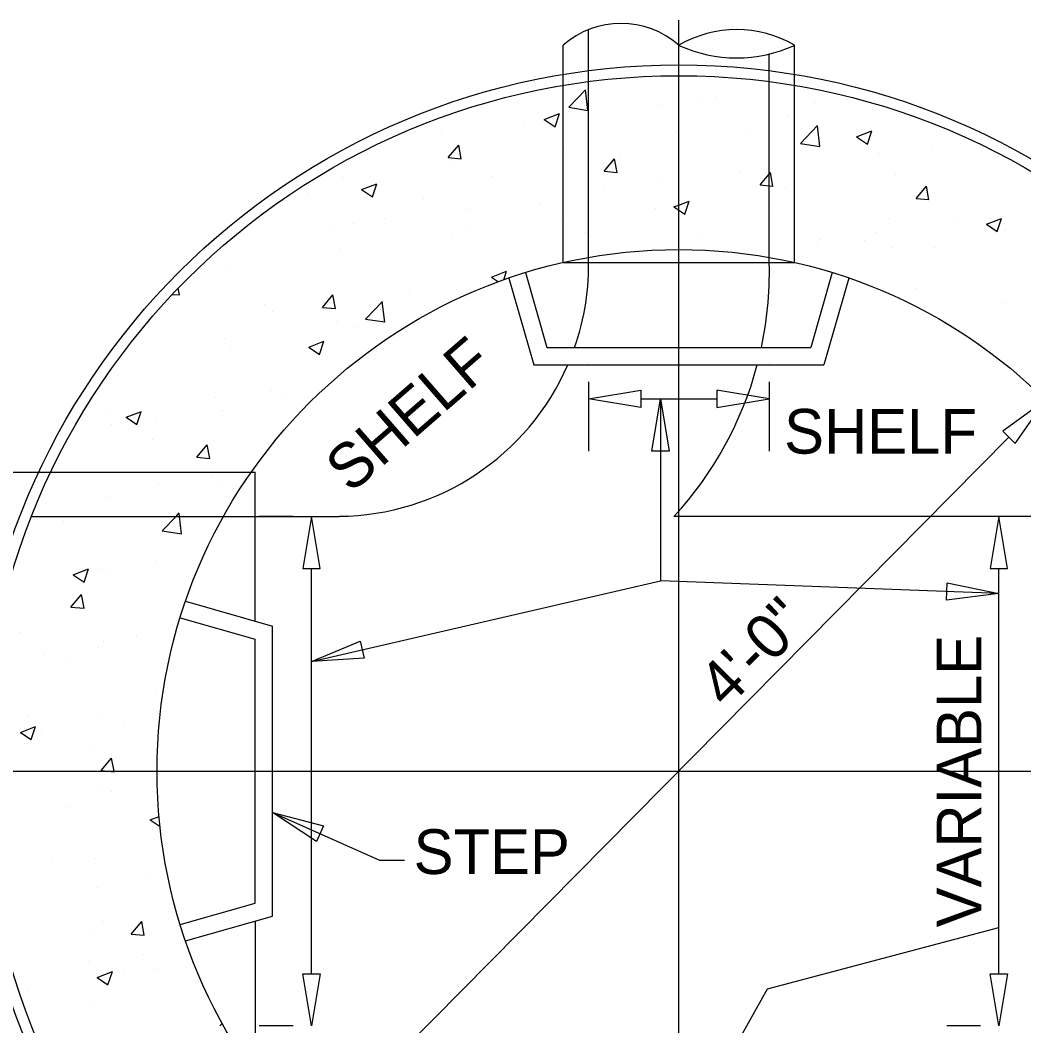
# Model space of a CAD drawing. Extents: x 6712067 to 6713867, y 1867712 to 1869162.
# Drawn here: x 6712906.2 to 6713040.8, y 1867989.4 to 1868124.3 of the extents above; entities that cross this region are included whole.
import ezdxf

# ---------------------------------------------------------------- set-up
doc = ezdxf.new("R2010")
doc.units = 0
for name, color, linetype in [('G-MARK', 7, 'Continuous'), ('G-TEXT', 7, 'Continuous'), ('Misc CnstDet(22)', 7, 'Continuous')]:
    doc.layers.add(name, color=color, linetype=linetype)

msp = doc.modelspace()

# ---------------------------------------------------------------- linework, layer by layer
at = {"layer": 'G-MARK'}
for p, q in [((6712982.44, 1868075.84), (6712982.44, 1868066.53)), ((6712989.44, 1868073.53), (6712999.64, 1868073.53)), ((6712992.07, 1868073.52), (6712992.07, 1868049.11)), ((6713038.81, 1868068.39), (6712950.27, 1867978.84)), ((6712945.28, 1867996.43), (6712945.28, 1868050.79)), ((6712945.28, 1868038.33), (6712992.07, 1868049.11)), ((6713037.47, 1868047.44), (6712992.07, 1868049.11))]:
    msp.add_line(p, q, dxfattribs=at)
msp.add_lwpolyline([(6712940.04, 1868018.07), (6712954.39, 1868011.66), (6712957.74, 1868011.66)], dxfattribs=at)
at = {"layer": 'G-TEXT'}
for points in [[(6712989.44, 1868074.7), (6712989.44, 1868072.36), (6712982.44, 1868073.53)], [(6712999.64, 1868074.7), (6712999.64, 1868072.36), (6713006.64, 1868073.53)], [(6712990.9, 1868066.52), (6712992.07, 1868073.52), (6712993.23, 1868066.52)], [(6713037.97, 1868069.2), (6713039.63, 1868067.56), (6713043.72, 1868073.35)], [(6712944.11, 1868050.79), (6712946.45, 1868050.79), (6712945.28, 1868057.78)], [(6713036.29, 1868050.79), (6713038.62, 1868050.79), (6713037.47, 1868057.78)], [(6713030.51, 1868048.86), (6713037.47, 1868047.44), (6713030.43, 1868046.53)], [(6712952.36, 1868038.76), (6712945.28, 1868038.33), (6712951.83, 1868041.04)], [(6712945.95, 1868014.15), (6712940.04, 1868018.07), (6712946.9, 1868016.28)], [(6712944.11, 1867996.43), (6712946.45, 1867996.43), (6712945.28, 1867989.43)], [(6713036.29, 1867996.43), (6713038.62, 1867996.43), (6713037.47, 1867989.43)]]:
    msp.add_lwpolyline(points, close=True, dxfattribs=at)
at = {"layer": 'Misc CnstDet(22)'}
for p, q in [((6712994.54, 1867921.43), (6712994.54, 1868124.34)), ((6712982.44, 1868092.51), (6712982.44, 1868123.08)), ((6712979.02, 1868091.82), (6712979.02, 1868120.97)), ((6713010.06, 1868091.82), (6713010.06, 1868120.97)), ((6713006.64, 1868092.51), (6713006.64, 1868119.8)), ((6712979.77, 1868112.65), (6712982.04, 1868115.01)), ((6712981.6, 1868114.6), (6712981.6, 1868114.6)), ((6712982.36, 1868112.24), (6712982.04, 1868115.01)), ((6713010.52, 1868115.47), (6713010.52, 1868115.47)), ((6712992.18, 1868113.06), (6712992.18, 1868113.06)), ((6712997.16, 1868113.94), (6712997.16, 1868113.94)), ((6712999.48, 1868114.02), (6712999.48, 1868114.02)), ((6713012.73, 1868113.28), (6713012.73, 1868113.28)), ((6712976.5, 1868111.02), (6712978.54, 1868111.81)), ((6712977.94, 1868110.04), (6712978.54, 1868111.8)), ((6712979.77, 1868112.65), (6712982.36, 1868112.24)), ((6713020.6, 1868112.18), (6713020.6, 1868112.18)), ((6712973.78, 1868110.64), (6712973.78, 1868110.64)), ((6712976.5, 1868111.02), (6712977.94, 1868110.04)), ((6713009.21, 1868111.42), (6713009.21, 1868111.42)), ((6713010.88, 1868107.81), (6713013.14, 1868110.19)), ((6713013.46, 1868107.41), (6713013.14, 1868110.18)), ((6712962.74, 1868109.18), (6712962.74, 1868109.18)), ((6712994.25, 1868109.36), (6712994.25, 1868109.36)), ((6713003.6, 1868109.26), (6713003.6, 1868109.26)), ((6713018.38, 1868108.69), (6713020.43, 1868109.47)), ((6713019.84, 1868107.7), (6713020.43, 1868109.47)), ((6712955.44, 1868108.22), (6712955.44, 1868108.22)), ((6712963.62, 1868105.9), (6712965.02, 1868107.57)), ((6712965.36, 1868105.75), (6712965.02, 1868107.57)), ((6713010.88, 1868107.81), (6713013.46, 1868107.41)), ((6713018.38, 1868108.69), (6713019.84, 1868107.71)), ((6712979.1, 1868107.17), (6712979.1, 1868107.17)), ((6712986.61, 1868106.35), (6712986.61, 1868106.35)), ((6713021.26, 1868106.4), (6713021.26, 1868106.4)), ((6713028.56, 1868107.36), (6713028.56, 1868107.36)), ((6712963.62, 1868105.9), (6712965.36, 1868105.75)), ((6712964.38, 1868105.31), (6712964.38, 1868105.31)), ((6712984.53, 1868104.07), (6712985.93, 1868105.75)), ((6712986.27, 1868103.91), (6712985.93, 1868105.74)), ((6712969.6, 1868103.42), (6712969.6, 1868103.42)), ((6712984.53, 1868104.07), (6712986.27, 1868103.91)), ((6713002.86, 1868103.97), (6713002.86, 1868103.97)), ((6713005.44, 1868102.24), (6713006.64, 1868103.68)), ((6713006.64, 1868103.68), (6713006.84, 1868103.91)), ((6713007.17, 1868102.09), (6713006.84, 1868103.91)), ((6713023.58, 1868103.58), (6713023.58, 1868103.58)), ((6712949.41, 1868103.26), (6712949.41, 1868103.26)), ((6712952.01, 1868101.62), (6712954.05, 1868102.4)), ((6712953.45, 1868100.64), (6712954.05, 1868102.4)), ((6712991.82, 1868102.52), (6712991.82, 1868102.52)), ((6713005.44, 1868102.24), (6713006.64, 1868102.13)), ((6713006.64, 1868102.13), (6713007.18, 1868102.09)), ((6713026.35, 1868100.41), (6713027.75, 1868102.09)), ((6713028.08, 1868100.25), (6713027.75, 1868102.09)), ((6712944.8, 1868101.02), (6712944.8, 1868101.02)), ((6712952.01, 1868101.62), (6712953.45, 1868100.64)), ((6712984.52, 1868101.56), (6712984.52, 1868101.56)), ((6713008.86, 1868101.71), (6713008.86, 1868101.71)), ((6712952.6, 1868100.5), (6712952.6, 1868100.5)), ((6712960.36, 1868100.35), (6712960.36, 1868100.35)), ((6712975.92, 1868099.7), (6712975.92, 1868099.7)), ((6712993.89, 1868099.65), (6712993.89, 1868099.65)), ((6712993.89, 1868099.29), (6712994.54, 1868099.53)), ((6712994.54, 1868099.53), (6712995.94, 1868100.07)), ((6712995.34, 1868098.3), (6712995.94, 1868100.07)), ((6713026.35, 1868100.41), (6713028.08, 1868100.26)), ((6712966.11, 1868099.14), (6712966.11, 1868099.14)), ((6712991.48, 1868099.05), (6712991.48, 1868099.05)), ((6712993.89, 1868099.29), (6712994.54, 1868098.85)), ((6712994.54, 1868098.85), (6712995.35, 1868098.3)), ((6713007.04, 1868098.39), (6713007.04, 1868098.39)), ((6712947.77, 1868096.73), (6712947.77, 1868096.73)), ((6712950.95, 1868097.11), (6712950.95, 1868097.11)), ((6712955.07, 1868097.68), (6712955.07, 1868097.68)), ((6712978.76, 1868097.47), (6712978.76, 1868097.47)), ((6713022.61, 1868097.73), (6713022.61, 1868097.73)), ((6713031.92, 1868097.31), (6713031.92, 1868097.31)), ((6713035.78, 1868096.95), (6713037.82, 1868097.73)), ((6713035.78, 1868096.95), (6713037.24, 1868095.97)), ((6713036.4, 1868097.7), (6713036.4, 1868097.7)), ((6713037.24, 1868095.97), (6713037.82, 1868097.73)), ((6713038.17, 1868097.07), (6713038.17, 1868097.07)), ((6712964.03, 1868095.6), (6712964.03, 1868095.6)), ((6712966.51, 1868096.44), (6712966.51, 1868096.44)), ((6712982.07, 1868095.79), (6712982.07, 1868095.79)), ((6713020.88, 1868095.87), (6713020.88, 1868095.87)), ((6713038.36, 1868096.06), (6713038.36, 1868096.06)), ((6712997.63, 1868095.13), (6712997.63, 1868095.13)), ((6713013.2, 1868094.47), (6713013.2, 1868094.47)), ((6713013.6, 1868094.9), (6713013.6, 1868094.9)), ((6713019.39, 1868094.79), (6713019.39, 1868094.79)), ((6712949.06, 1868093.55), (6712949.06, 1868093.55)), ((6713023.23, 1868093.87), (6713023.23, 1868093.87)), ((6713028.76, 1868093.81), (6713028.76, 1868093.81)), ((6712933.92, 1868091.37), (6712933.92, 1868091.37)), ((6712979.02, 1868091.82), (6713010.06, 1868091.82)), ((6712969.4, 1868089.88), (6712971.45, 1868090.67)), ((6712971.06, 1868089.5), (6712971.45, 1868090.66)), ((6712973.98, 1868090.47), (6712976.84, 1868080.44)), ((6713015.1, 1868090.47), (6713012.24, 1868080.44)), ((6712969.4, 1868089.88), (6712970.34, 1868089.25)), ((6712971.76, 1868089.75), (6712975.08, 1868078.11)), ((6713017.33, 1868089.75), (6713014, 1868078.11)), ((6712926.64, 1868087.56), (6712927.6, 1868087.48)), ((6712927.6, 1868087.48), (6712927.42, 1868088.39)), ((6712946.76, 1868085.8), (6712948.16, 1868087.48)), ((6712948.49, 1868085.64), (6712948.16, 1868087.48)), ((6712958.43, 1868087.64), (6712958.43, 1868087.64)), ((6713026.38, 1868088.39), (6713026.38, 1868088.39)), ((6712939, 1868086.2), (6712939, 1868086.2)), ((6712947.39, 1868086.18), (6712947.39, 1868086.18)), ((6712952.52, 1868084.25), (6712954.79, 1868086.62)), ((6712955.12, 1868083.84), (6712954.78, 1868086.62)), ((6713038.01, 1868086.35), (6713038.01, 1868086.35)), ((6712940.1, 1868085.23), (6712940.1, 1868085.23)), ((6712946.76, 1868085.8), (6712948.49, 1868085.65)), ((6712954.56, 1868085.54), (6712954.56, 1868085.54)), ((6712948.71, 1868083.85), (6712948.71, 1868083.85)), ((6712952.52, 1868084.25), (6712955.12, 1868083.85)), ((6712951.4, 1868083.11), (6712951.4, 1868083.11)), ((6712933.56, 1868081.66), (6712933.56, 1868081.66)), ((6712944.91, 1868080.48), (6712946.96, 1868081.26)), ((6712944.91, 1868080.48), (6712946.36, 1868079.5)), ((6712946.36, 1868079.5), (6712946.96, 1868081.26)), ((6712934.4, 1868080.19), (6712934.4, 1868080.19)), ((6712976.84, 1868080.44), (6713012.24, 1868080.44)), ((6712975.08, 1868078.11), (6713014, 1868078.11)), ((6712982.44, 1868078.3), (6712982.44, 1868078.3)), ((6713006.64, 1868078.3), (6713006.64, 1868078.3)), ((6713006.64, 1868075.84), (6713006.64, 1868066.53)), ((6712932.43, 1868073.73), (6712932.43, 1868073.73)), ((6712939.73, 1868074.69), (6712939.73, 1868074.69)), ((6712941.38, 1868073.8), (6712941.38, 1868073.8)), ((6713006.64, 1868073.53), (6713006.64, 1868073.53)), ((6712917.77, 1868071.96), (6712917.77, 1868071.96)), ((6712920.42, 1868071.08), (6712922.47, 1868071.86)), ((6712920.42, 1868071.08), (6712921.87, 1868070.1)), ((6712921.87, 1868070.09), (6712922.45, 1868071.86)), ((6712933.21, 1868071.96), (6712933.21, 1868071.96)), ((6712933.32, 1868071.31), (6712933.32, 1868071.31)), ((6712918.48, 1868070.09), (6712918.48, 1868070.09)), ((6712924.38, 1868070.87), (6712924.38, 1868070.87)), ((6712923.91, 1868068.05), (6712923.91, 1868068.05)), ((6712929.89, 1868065.71), (6712931.3, 1868067.38)), ((6712931.64, 1868065.55), (6712931.3, 1868067.37)), ((6712939.47, 1868067.38), (6712939.47, 1868067.38)), ((6712929.89, 1868065.71), (6712931.64, 1868065.55)), ((6712880.72, 1868063.69), (6712908.71, 1868063.69)), ((6712908.71, 1868063.69), (6712937.71, 1868063.69)), ((6712932.06, 1868063.2), (6712932.06, 1868063.2)), ((6712937.71, 1868043.73), (6712937.71, 1868063.69)), ((6712924.76, 1868062.23), (6712924.76, 1868062.23)), ((6712932.86, 1868062.25), (6712932.86, 1868062.25)), ((6712918.14, 1868060.4), (6712918.14, 1868060.4)), ((6712907.75, 1868057.78), (6712933.49, 1868057.78)), ((6712918.52, 1868057.76), (6712918.52, 1868057.76)), ((6712925.28, 1868055.85), (6712927.13, 1868057.78)), ((6712927.13, 1868057.78), (6712927.55, 1868058.23)), ((6712927.6, 1868057.78), (6712927.54, 1868058.21)), ((6712927.87, 1868055.45), (6712927.6, 1868057.78)), ((6712933.49, 1868057.78), (6712949, 1868057.78)), ((6712942.83, 1868057.78), (6712938.28, 1868057.78)), ((6712945.28, 1868057.78), (6712945.28, 1868057.78)), ((6712945.28, 1868057.78), (6712945.28, 1868057.78)), ((6713055.59, 1868057.78), (6712993.89, 1868057.78)), ((6713035.01, 1868057.78), (6713030.46, 1868057.78)), ((6713037.47, 1868057.78), (6713037.47, 1868057.78)), ((6713037.47, 1868057.78), (6713037.47, 1868057.78)), ((6712911.97, 1868057.15), (6712911.97, 1868057.15)), ((6712927.53, 1868056.49), (6712927.53, 1868056.49)), ((6712925.28, 1868055.85), (6712927.87, 1868055.45)), ((6712924.39, 1868051.7), (6712924.39, 1868051.7)), ((6713037.47, 1867996.43), (6713037.47, 1868050.79)), ((6712913.33, 1868049.94), (6712915.37, 1868050.72)), ((6712913.33, 1868049.94), (6712914.78, 1868048.97)), ((6712914.78, 1868048.97), (6712915.36, 1868050.72)), ((6712917.1, 1868050.73), (6712917.1, 1868050.73)), ((6712917.78, 1868050.69), (6712917.78, 1868050.69)), ((6712913.03, 1868045.6), (6712914.43, 1868047.28)), ((6712914.78, 1868045.45), (6712914.43, 1868047.28)), ((6712913.03, 1868045.6), (6712914.78, 1868045.45)), ((6712928.4, 1868046.38), (6712940.04, 1868043.07)), ((6712927.68, 1868044.17), (6712937.71, 1868041.3)), ((6712940.04, 1868004.15), (6712940.04, 1868043.07)), ((6712906.3, 1868042.25), (6712906.3, 1868042.25)), ((6712921.85, 1868041.6), (6712921.85, 1868041.6)), ((6712916.73, 1868040.2), (6712916.73, 1868040.2)), ((6712917.31, 1868040.37), (6712917.31, 1868040.37)), ((6712917.43, 1868040.99), (6712917.43, 1868040.99)), ((6712937.71, 1868005.91), (6712937.71, 1868041.3)), ((6712909.43, 1868039.23), (6712909.43, 1868039.23)), ((6712912.44, 1868038.34), (6712912.44, 1868038.34)), ((6712924.3, 1868033.97), (6712924.3, 1868033.97)), ((6712907.3, 1868031.05), (6712907.3, 1868031.05)), ((6712917.07, 1868031.28), (6712917.07, 1868031.28)), ((6712906.24, 1868028.8), (6712908.27, 1868029.58)), ((6712907.69, 1868027.83), (6712908.27, 1868029.58)), ((6712920.09, 1868030.16), (6712920.09, 1868030.16)), ((6712906.24, 1868028.8), (6712907.69, 1868027.83)), ((6712909.05, 1868028.7), (6712909.05, 1868028.7)), ((6712916.05, 1868026.78), (6712916.05, 1868026.78)), ((6712917.07, 1868023.68), (6712918.48, 1868025.36)), ((6712918.81, 1868023.6), (6712918.48, 1868025.36)), ((6712876.34, 1868023.6), (6713115.5, 1868023.6)), ((6712917.07, 1868023.68), (6712917.96, 1868023.6)), ((6712917.96, 1868023.6), (6712918.82, 1868023.53)), ((6712918.82, 1868023.52), (6712918.81, 1868023.6)), ((6712916.72, 1868021.57), (6712916.72, 1868021.57)), ((6712918.43, 1868020.85), (6712918.43, 1868020.85)), ((6712912.42, 1868018.66), (6712912.42, 1868018.66)), ((6712923.64, 1868017.06), (6712924.85, 1868017.53)), ((6712923.64, 1868017.06), (6712924.98, 1868016.16)), ((6712910.38, 1868011.89), (6712910.38, 1868011.89)), ((6712916.36, 1868011.87), (6712916.36, 1868011.87)), ((6712923.17, 1868009.59), (6712923.17, 1868009.59)), ((6712916.52, 1868007.96), (6712916.52, 1868007.96)), ((6712927.68, 1868003.04), (6712937.71, 1868005.91)), ((6712928.4, 1868000.82), (6712940.04, 1868004.15)), ((6712917.23, 1868003.45), (6712917.23, 1868003.45)), ((6712921.12, 1868001.75), (6712922.52, 1868003.43)), ((6712922.86, 1868001.6), (6712922.52, 1868003.43)), ((6712937.71, 1868003.49), (6712937.71, 1867983.53)), ((6712916.01, 1868002.17), (6712916.01, 1868002.17)), ((6712921.12, 1868001.75), (6712922.86, 1868001.6)), ((6712922.8, 1867999.06), (6712922.8, 1867999.06)), ((6712915.5, 1867998.09), (6712915.5, 1867998.09)), ((6712924.21, 1867997.06), (6712924.21, 1867997.06)), ((6712916.54, 1867995.93), (6712918.59, 1867996.72)), ((6712916.54, 1867995.93), (6712917.99, 1867994.95)), ((6712917.99, 1867994.95), (6712918.58, 1867996.72)), ((6712920.14, 1867996.41), (6712920.14, 1867996.41)), ((6712907.21, 1867994.13), (6712907.21, 1867994.13)), ((6712930.37, 1867994.33), (6712930.37, 1867994.33)), ((6712915.65, 1867992.47), (6712915.65, 1867992.47)), ((6712933.01, 1867989.43), (6712933.32, 1867989.75)), ((6712942.83, 1867989.43), (6712938.28, 1867989.43)), ((6712945.28, 1867989.43), (6712945.28, 1867989.43)), ((6713035.01, 1867989.43), (6713030.46, 1867989.43)), ((6713037.47, 1867989.43), (6713037.47, 1867989.43))]:
    msp.add_line(p, q, dxfattribs=at)
msp.add_lwpolyline([(6712994.54, 1867973.11), (6713006.42, 1867994.39), (6713037.47, 1868002.61)], dxfattribs=at)
for radius in [94.73, 93.28, 69.96]:
    msp.add_circle((6712994.54, 1868023.61), radius, dxfattribs=at)
for centre, radius, start, end in [((6712986.78, 1868112.2), 11.71, 48.4565, 131.5435), ((6713002.3, 1868107.76), 15.32, 59.5444, 120.4556), ((6713002.3, 1868138.1), 18.82, 245.6342, 294.3658), ((6712948.67, 1868091.56), 33.78, 340.7867, 1.6032), ((6712958.31, 1868090.55), 48.38, 347.9482, 2.3241), ((6712948.67, 1868091.56), 33.78, 270.5518, 336.5396), ((6712958.31, 1868090.55), 48.38, 317.3685, 345.1079)]:
    msp.add_arc(centre, radius, start, end, dxfattribs=at)

# ---------------------------------------------------------------- texts
for s, rotation, p in [('SHELF', 41.0189, (6712950.53, 1868060.74)), ('4\'-0"', 45.3287, (6713000.94, 1868031.83)), ('VARIABLE', 90, (6713035.12, 1868002.64))]:
    msp.add_text(s, height=6, rotation=rotation, dxfattribs=at).set_placement(p)
for s, p in [('SHELF', (6713008.66, 1868066.19)), ('STEP', (6712958.98, 1868009.8))]:
    msp.add_text(s, height=6, dxfattribs=at).set_placement(p)

doc.saveas('drawing.dxf')
